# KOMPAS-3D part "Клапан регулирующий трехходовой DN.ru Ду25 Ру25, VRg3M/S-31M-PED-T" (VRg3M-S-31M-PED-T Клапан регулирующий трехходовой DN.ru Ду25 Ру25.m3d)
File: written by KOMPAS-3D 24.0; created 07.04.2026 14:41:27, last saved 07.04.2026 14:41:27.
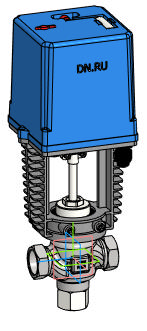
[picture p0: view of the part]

Document properties: Автор: DN.RU; Полное имя файла: D:\PROJECT CAD\DN.RU\...197(ACTUALE). VRg3M-S-31M-PED-T Клапан регулирующий трехходовой DN.ru\Исходники\DN25\VRg3M-S-31M-PED-T Клапан регулирующий трехходовой DN.ru Ду25 Ру25.m3d

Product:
- Body: Твердое тело1  | qty 1
    Масса: 19.668634
- Part/product: Клапан регулирующий трехходовой DN.ru Ду25 Ру25  | designation VRg3M/S-31M-PED-T
    Масса: 3.4
    Раздел спецификации: Прочие изделия
    Комментарий: D230-11265
    Примечание: D230-11265
    additional columns: Типовые

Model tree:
1. Твердое тело1  (labels: Твердое тело1)

Expressions: VRg3M/S-31M-PED-T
